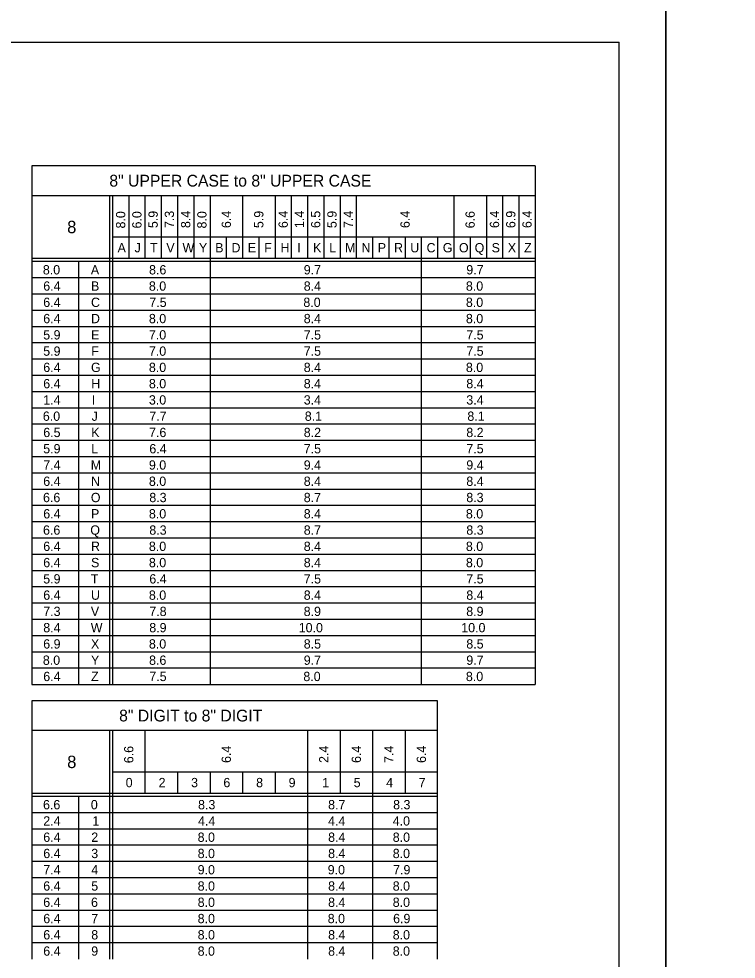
# Model space of a CAD drawing. Extents: x 638421 to 641849, y 297270 to 299646.
# Drawn here: x 640735.4 to 640967.1, y 298740.6 to 299044.1 of the extents above; entities that cross this region are included whole.
import ezdxf

# ---------------------------------------------------------------- set-up
doc = ezdxf.new("R2010")
doc.units = 0
for name, color, linetype in [('1', 7, 'Continuous'), ('2', 7, 'Continuous'), ('XCS-GRID-HVGL', 7, 'Continuous')]:
    doc.layers.add(name, color=color, linetype=linetype)

msp = doc.modelspace()

# ---------------------------------------------------------------- linework, layer by layer
at = {"layer": '1'}
for p in [(640143.31, 299036.63), (640929.31, 298472.63)]:
    msp.add_line(p, (640929.31, 299036.63), dxfattribs=at)
at = {"layer": '2'}
for p, q in [((640902.11, 298996.63), (640739.61, 298996.63)), ((640739.61, 298996.63), (640739.61, 298829.25)), ((640902.11, 298996.63), (640902.11, 298829.25)), ((640739.61, 298987.13), (640902.11, 298987.13)), ((640764.61, 298987.13), (640764.61, 298829.25)), ((640765.61, 298987.13), (640765.61, 298829.25)), ((640770.86, 298987.13), (640770.86, 298966.75)), ((640776.11, 298987.13), (640776.11, 298966.75)), ((640781.36, 298987.13), (640781.36, 298966.75)), ((640786.61, 298987.13), (640786.61, 298966.75)), ((640791.86, 298987.13), (640791.86, 298966.75)), ((640797.11, 298987.13), (640797.11, 298829.25)), ((640807.61, 298987.13), (640807.61, 298966.75)), ((640818.11, 298987.13), (640818.11, 298966.75)), ((640823.36, 298987.13), (640823.36, 298966.75)), ((640828.61, 298987.13), (640828.61, 298966.75)), ((640833.86, 298987.13), (640833.86, 298966.75)), ((640839.11, 298987.13), (640839.11, 298966.75)), ((640844.36, 298987.13), (640844.36, 298966.75)), ((640875.86, 298987.13), (640875.86, 298966.75)), ((640886.36, 298987.13), (640886.36, 298966.75)), ((640891.61, 298987.13), (640891.61, 298966.75)), ((640896.86, 298987.13), (640896.86, 298966.75)), ((640765.61, 298973.75), (640902.11, 298973.75)), ((640802.36, 298973.75), (640802.36, 298966.75)), ((640812.86, 298973.75), (640812.86, 298966.75)), ((640849.61, 298973.75), (640849.61, 298966.75)), ((640854.86, 298973.75), (640854.86, 298966.75)), ((640860.11, 298973.75), (640860.11, 298966.75)), ((640860.11, 298973.75), (640860.11, 298966.75)), ((640865.36, 298973.75), (640865.36, 298829.25)), ((640870.61, 298973.75), (640870.61, 298966.75)), ((640881.11, 298973.75), (640881.11, 298966.75)), ((640902.11, 298966.75), (640739.61, 298966.75)), ((640902.11, 298965.75), (640739.61, 298965.75)), ((640754.61, 298965.75), (640754.61, 298829.25)), ((640902.11, 298960.5), (640739.61, 298960.5)), ((640902.11, 298955.25), (640739.61, 298955.25)), ((640902.11, 298950), (640739.61, 298950)), ((640902.11, 298944.75), (640739.61, 298944.75)), ((640902.11, 298939.5), (640739.61, 298939.5)), ((640902.11, 298934.25), (640739.61, 298934.25)), ((640902.11, 298929), (640739.61, 298929)), ((640902.11, 298923.75), (640739.61, 298923.75)), ((640902.11, 298918.5), (640739.61, 298918.5)), ((640902.11, 298913.25), (640739.61, 298913.25)), ((640902.11, 298908), (640739.61, 298908)), ((640902.11, 298902.75), (640739.61, 298902.75)), ((640902.11, 298897.5), (640739.61, 298897.5)), ((640902.11, 298892.25), (640739.61, 298892.25)), ((640902.11, 298887), (640739.61, 298887)), ((640902.11, 298881.75), (640739.61, 298881.75)), ((640902.11, 298876.5), (640739.61, 298876.5)), ((640902.11, 298871.25), (640739.61, 298871.25)), ((640902.11, 298866), (640739.61, 298866)), ((640902.11, 298860.75), (640739.61, 298860.75)), ((640902.11, 298855.5), (640739.61, 298855.5)), ((640902.11, 298850.25), (640739.61, 298850.25)), ((640902.11, 298845), (640739.61, 298845)), ((640902.11, 298839.75), (640739.61, 298839.75)), ((640902.11, 298834.5), (640739.61, 298834.5)), ((640739.61, 298829.25), (640739.61, 298829.25)), ((640739.61, 298829.25), (640902.11, 298829.25)), ((640870.61, 298824), (640739.61, 298824)), ((640739.61, 298824), (640739.61, 298740.63)), ((640870.61, 298740.63), (640870.61, 298824)), ((640739.61, 298814.5), (640870.61, 298814.5)), ((640764.61, 298814.5), (640764.61, 298740.63)), ((640765.61, 298814.5), (640765.61, 298740.63)), ((640776.11, 298814.5), (640776.11, 298794.13)), ((640828.61, 298814.5), (640828.61, 298740.63)), ((640839.11, 298814.5), (640839.11, 298794.13)), ((640849.61, 298814.5), (640849.61, 298740.63)), ((640860.11, 298814.5), (640860.11, 298794.13)), ((640765.61, 298801.13), (640870.61, 298801.13)), ((640786.61, 298801.13), (640786.61, 298794.13)), ((640797.11, 298801.13), (640797.11, 298794.13)), ((640807.61, 298801.13), (640807.61, 298794.13)), ((640818.11, 298801.13), (640818.11, 298794.13)), ((640870.61, 298794.13), (640739.61, 298794.13)), ((640870.61, 298793.13), (640739.61, 298793.13)), ((640754.61, 298793.13), (640754.61, 298740.63)), ((640870.61, 298787.88), (640739.61, 298787.88)), ((640870.61, 298782.63), (640739.61, 298782.63)), ((640870.61, 298777.38), (640739.61, 298777.38)), ((640870.61, 298772.13), (640739.61, 298772.13)), ((640870.61, 298766.88), (640739.61, 298766.88)), ((640870.61, 298761.63), (640739.61, 298761.63)), ((640870.61, 298756.38), (640739.61, 298756.38)), ((640870.61, 298751.13), (640739.61, 298751.13)), ((640870.61, 298745.88), (640739.61, 298745.88))]:
    msp.add_line(p, q, dxfattribs=at)
at = {"layer": 'XCS-GRID-HVGL'}
for points in [[(640103.31, 299051.63), (640944.31, 299051.63), (640944.31, 298457.63), (640103.31, 298457.63)], [(640944.31, 299051.63), (641785.31, 299051.63), (641785.31, 298457.63), (640944.31, 298457.63)]]:
    msp.add_lwpolyline(points, close=True, dxfattribs=at)

# ---------------------------------------------------------------- texts
at = {"layer": '2'}
for s, height, p in [('8" UPPER CASE to 8" UPPER CASE', 3.8, (640764.6, 298989.98)), ('8', 4, (640750.98, 298974.94)), ('A', 3, (640767.26, 298968.75)), ('J', 3, (640772.74, 298968.75)), ('T', 3, (640777.74, 298968.75)), ('V', 3, (640783.01, 298968.75)), ('W', 3, (640788.23, 298968.75)), ('Y', 3, (640793.54, 298968.75)), ('B', 3, (640798.8, 298968.75)), ('D', 3, (640804.05, 298968.75)), ('E', 3, (640809.32, 298968.75)), ('F', 3, (640814.62, 298968.75)), ('H', 3, (640819.89, 298968.75)), ('I', 3, (640825.3, 298968.75)), ('K', 3, (640830.39, 298968.75)), ('L', 3, (640835.64, 298968.75)), ('M', 3, (640840.73, 298968.75)), ('N', 3, (640846.05, 298968.75)), ('P', 3, (640851.3, 298968.75)), ('R', 3, (640856.55, 298968.75)), ('U', 3, (640861.79, 298968.75)), ('C', 3, (640867.05, 298968.75)), ('G', 3, (640872.3, 298968.75)), ('O', 3, (640877.51, 298968.75)), ('Q', 3, (640882.58, 298968.75)), ('S', 3, (640888.07, 298968.75)), ('X', 3, (640893.29, 298968.75)), ('Z', 3, (640898.55, 298968.75)), ('8.0', 3, (640743.13, 298961.63)), ('A', 3, (640758.63, 298961.63)), ('8.6', 3, (640777.43, 298961.63)), ('9.7', 3, (640827.39, 298961.63)), ('9.7', 3, (640879.89, 298961.63)), ('6.4', 3, (640743.26, 298956.38)), ('B', 3, (640758.68, 298956.38)), ('8.0', 3, (640777.38, 298956.38)), ('8.4', 3, (640827.39, 298956.38)), ('8.0', 3, (640879.76, 298956.38)), ('6.4', 3, (640743.26, 298951.13)), ('C', 3, (640758.68, 298951.13)), ('7.5', 3, (640777.51, 298951.13)), ('8.0', 3, (640827.26, 298951.13)), ('8.0', 3, (640879.76, 298951.13)), ('6.4', 3, (640743.26, 298945.88)), ('D', 3, (640758.68, 298945.88)), ('8.0', 3, (640777.38, 298945.88)), ('8.4', 3, (640827.39, 298945.88)), ('8.0', 3, (640879.76, 298945.88)), ('5.9', 3, (640743.25, 298940.63)), ('E', 3, (640758.69, 298940.63)), ('7.0', 3, (640777.38, 298940.63)), ('7.5', 3, (640827.39, 298940.63)), ('7.5', 3, (640879.89, 298940.63)), ('5.9', 3, (640743.25, 298935.38)), ('F', 3, (640758.75, 298935.38)), ('7.0', 3, (640777.38, 298935.38)), ('7.5', 3, (640827.39, 298935.38)), ('7.5', 3, (640879.89, 298935.38)), ('6.4', 3, (640743.26, 298930.13)), ('G', 3, (640758.68, 298930.13)), ('8.0', 3, (640777.38, 298930.13)), ('8.4', 3, (640827.39, 298930.13)), ('8.0', 3, (640879.76, 298930.13)), ('6.4', 3, (640743.26, 298924.88)), ('H', 3, (640758.76, 298924.88)), ('8.0', 3, (640777.38, 298924.88)), ('8.4', 3, (640827.39, 298924.88)), ('8.4', 3, (640879.89, 298924.88)), ('1.4', 3, (640743.26, 298919.63)), ('I', 3, (640758.93, 298919.63)), ('3.0', 3, (640777.38, 298919.63)), ('3.4', 3, (640827.39, 298919.63)), ('3.4', 3, (640879.89, 298919.63)), ('6.0', 3, (640743.13, 298914.38)), ('J', 3, (640758.87, 298914.38)), ('7.7', 3, (640777.51, 298914.38)), ('8.1', 3, (640827.73, 298914.38)), ('8.1', 3, (640880.23, 298914.38)), ('6.5', 3, (640743.26, 298909.13)), ('K', 3, (640758.76, 298909.13)), ('7.6', 3, (640777.43, 298909.13)), ('8.2', 3, (640827.39, 298909.13)), ('8.2', 3, (640879.89, 298909.13)), ('5.9', 3, (640743.25, 298903.88)), ('L', 3, (640758.76, 298903.88)), ('6.4', 3, (640777.51, 298903.88)), ('7.5', 3, (640827.39, 298903.88)), ('7.5', 3, (640879.89, 298903.88)), ('7.4', 3, (640743.26, 298898.63)), ('M', 3, (640758.61, 298898.63)), ('9.0', 3, (640777.38, 298898.63)), ('9.4', 3, (640827.39, 298898.63)), ('9.4', 3, (640879.89, 298898.63)), ('6.4', 3, (640743.26, 298893.38)), ('N', 3, (640758.68, 298893.38)), ('8.0', 3, (640777.38, 298893.38)), ('8.4', 3, (640827.39, 298893.38)), ('8.4', 3, (640879.89, 298893.38)), ('6.6', 3, (640743.18, 298888.13)), ('O', 3, (640758.63, 298888.13)), ('8.3', 3, (640777.51, 298888.13)), ('8.7', 3, (640827.39, 298888.13)), ('8.3', 3, (640879.89, 298888.13)), ('6.4', 3, (640743.26, 298882.88)), ('P', 3, (640758.68, 298882.88)), ('8.0', 3, (640777.38, 298882.88)), ('8.4', 3, (640827.39, 298882.88)), ('8.0', 3, (640879.76, 298882.88)), ('6.6', 3, (640743.18, 298877.63)), ('Q', 3, (640758.45, 298877.63)), ('8.3', 3, (640777.51, 298877.63)), ('8.7', 3, (640827.39, 298877.63)), ('8.3', 3, (640879.89, 298877.63)), ('6.4', 3, (640743.26, 298872.38)), ('R', 3, (640758.68, 298872.38)), ('8.0', 3, (640777.38, 298872.38)), ('8.4', 3, (640827.39, 298872.38)), ('8.0', 3, (640879.76, 298872.38)), ('6.4', 3, (640743.26, 298867.13)), ('S', 3, (640758.69, 298867.13)), ('8.0', 3, (640777.38, 298867.13)), ('8.4', 3, (640827.39, 298867.13)), ('8.0', 3, (640879.76, 298867.13)), ('5.9', 3, (640743.25, 298861.88)), ('T', 3, (640758.62, 298861.88)), ('6.4', 3, (640777.51, 298861.88)), ('7.5', 3, (640827.39, 298861.88)), ('7.5', 3, (640879.89, 298861.88)), ('6.4', 3, (640743.26, 298856.63)), ('U', 3, (640758.67, 298856.63)), ('8.0', 3, (640777.38, 298856.63)), ('8.4', 3, (640827.39, 298856.63)), ('8.4', 3, (640879.89, 298856.63)), ('7.3', 3, (640743.26, 298851.38)), ('V', 3, (640758.63, 298851.38)), ('7.8', 3, (640777.51, 298851.38)), ('8.9', 3, (640827.37, 298851.38)), ('8.9', 3, (640879.87, 298851.38)), ('8.4', 3, (640743.26, 298846.13)), ('W', 3, (640758.61, 298846.13)), ('8.9', 3, (640777.5, 298846.13)), ('10.0', 3, (640825.76, 298846.13)), ('10.0', 3, (640878.26, 298846.13)), ('6.9', 3, (640743.25, 298840.88)), ('X', 3, (640758.67, 298840.88)), ('8.0', 3, (640777.38, 298840.88)), ('8.5', 3, (640827.39, 298840.88)), ('8.5', 3, (640879.89, 298840.88)), ('8.0', 3, (640743.13, 298835.63)), ('Y', 3, (640758.67, 298835.63)), ('8.6', 3, (640777.43, 298835.63)), ('9.7', 3, (640827.39, 298835.63)), ('9.7', 3, (640879.89, 298835.63)), ('6.4', 3, (640743.26, 298830.38)), ('Z', 3, (640758.68, 298830.38)), ('7.5', 3, (640777.51, 298830.38)), ('8.0', 3, (640827.26, 298830.38)), ('8.0', 3, (640879.76, 298830.38)), ('8" DIGIT to 8" DIGIT', 3.8, (640767.76, 298817.35)), ('8', 4, (640750.98, 298802.31)), ('0', 3, (640769.88, 298796.13)), ('2', 3, (640780.51, 298796.13)), ('3', 3, (640791.01, 298796.13)), ('6', 3, (640801.43, 298796.13)), ('8', 3, (640812.01, 298796.13)), ('9', 3, (640822.5, 298796.13)), ('1', 3, (640833.35, 298796.13)), ('5', 3, (640843.51, 298796.13)), ('4', 3, (640854.01, 298796.13)), ('7', 3, (640864.51, 298796.13)), ('6.6', 3, (640743.18, 298789)), ('0', 3, (640758.63, 298789)), ('8.3', 3, (640793.26, 298789)), ('8.7', 3, (640835.26, 298789)), ('8.3', 3, (640856.26, 298789)), ('2.4', 3, (640743.26, 298783.75)), ('1', 3, (640759.1, 298783.75)), ('4.4', 3, (640793.26, 298783.75)), ('4.4', 3, (640835.26, 298783.75)), ('4.0', 3, (640856.13, 298783.75)), ('6.4', 3, (640743.26, 298778.5)), ('2', 3, (640758.76, 298778.5)), ('8.0', 3, (640793.13, 298778.5)), ('8.4', 3, (640835.26, 298778.5)), ('8.0', 3, (640856.13, 298778.5)), ('6.4', 3, (640743.26, 298773.25)), ('3', 3, (640758.76, 298773.25)), ('8.0', 3, (640793.13, 298773.25)), ('8.4', 3, (640835.26, 298773.25)), ('8.0', 3, (640856.13, 298773.25)), ('7.4', 3, (640743.26, 298768)), ('4', 3, (640758.76, 298768)), ('9.0', 3, (640793.13, 298768)), ('9.0', 3, (640835.13, 298768)), ('7.9', 3, (640856.25, 298768)), ('6.4', 3, (640743.26, 298762.75)), ('5', 3, (640758.76, 298762.75)), ('8.0', 3, (640793.13, 298762.75)), ('8.4', 3, (640835.26, 298762.75)), ('8.0', 3, (640856.13, 298762.75)), ('6.4', 3, (640743.26, 298757.5)), ('6', 3, (640758.68, 298757.5)), ('8.0', 3, (640793.13, 298757.5)), ('8.4', 3, (640835.26, 298757.5)), ('8.0', 3, (640856.13, 298757.5)), ('6.4', 3, (640743.26, 298752.25)), ('7', 3, (640758.76, 298752.25)), ('8.0', 3, (640793.13, 298752.25)), ('8.0', 3, (640835.13, 298752.25)), ('6.9', 3, (640856.25, 298752.25)), ('6.4', 3, (640743.26, 298747)), ('8', 3, (640758.76, 298747)), ('8.0', 3, (640793.13, 298747)), ('8.4', 3, (640835.26, 298747)), ('8.0', 3, (640856.13, 298747)), ('6.4', 3, (640743.26, 298741.75)), ('9', 3, (640758.75, 298741.75)), ('8.0', 3, (640793.13, 298741.75)), ('8.4', 3, (640835.26, 298741.75)), ('8.0', 3, (640856.13, 298741.75))]:
    msp.add_text(s, height=height, dxfattribs=at).set_placement(p)
for s, p in [('8.0', (640769.74, 298976.46)), ('6.0', (640774.99, 298976.46)), ('5.9', (640780.24, 298976.58)), ('7.3', (640785.49, 298976.59)), ('8.4', (640790.74, 298976.59)), ('8.0', (640795.99, 298976.46)), ('6.4', (640803.86, 298976.59)), ('5.9', (640814.36, 298976.58)), ('6.4', (640822.24, 298976.59)), ('1.4', (640827.49, 298976.59)), ('6.5', (640832.74, 298976.59)), ('5.9', (640837.99, 298976.58)), ('7.4', (640843.24, 298976.59)), ('6.4', (640861.61, 298976.59)), ('6.6', (640882.61, 298976.51)), ('6.4', (640890.49, 298976.59)), ('6.9', (640895.74, 298976.58)), ('6.4', (640900.99, 298976.59)), ('6.6', (640772.36, 298803.88)), ('6.4', (640803.86, 298803.96)), ('2.4', (640835.36, 298803.96)), ('6.4', (640845.86, 298803.96)), ('7.4', (640856.36, 298803.96)), ('6.4', (640866.86, 298803.96))]:
    msp.add_text(s, height=3, rotation=90, dxfattribs=at).set_placement(p)

doc.saveas('drawing.dxf')
